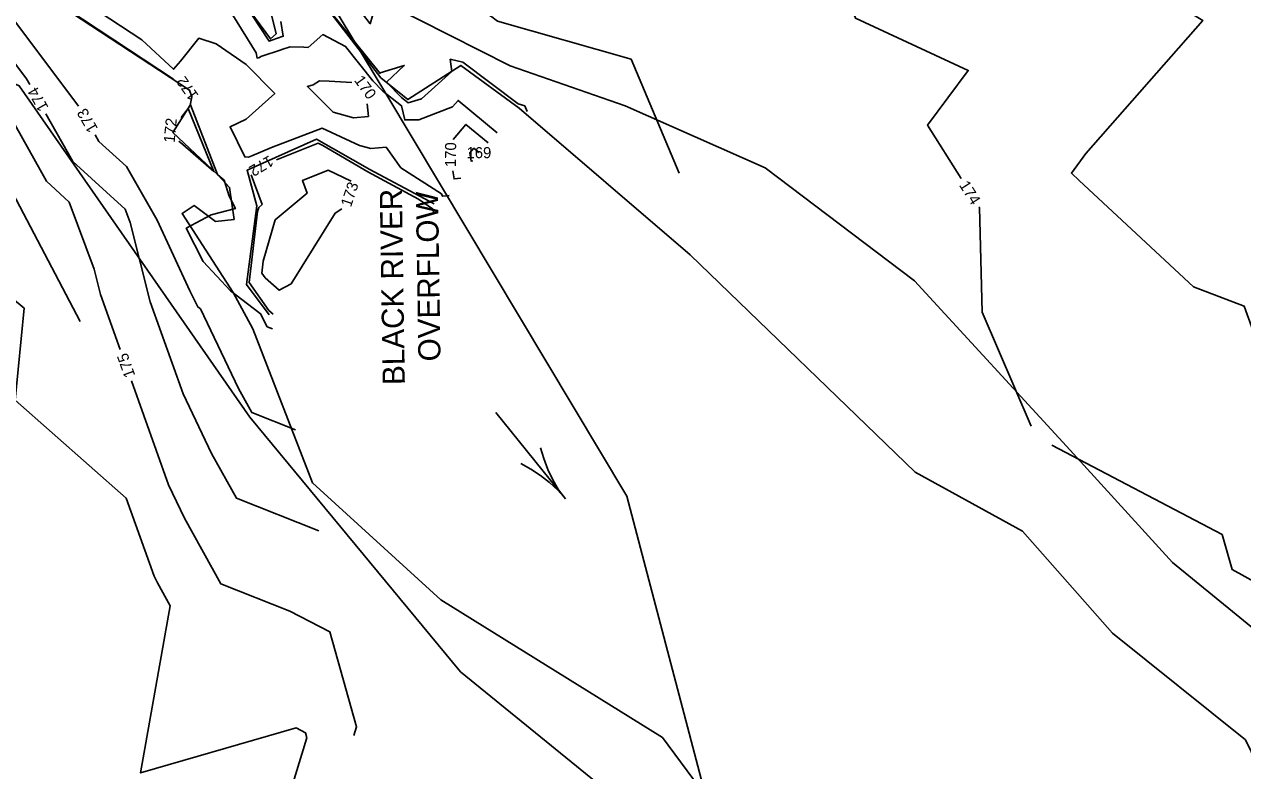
# Model space of a CAD drawing. Extents: x 2086416 to 2115205, y 575507 to 632762.
# Drawn here: x 2111556.7 to 2111776.5, y 581467.3 to 581601.8 of the extents above; entities that cross this region are included whole.
import ezdxf

# ---------------------------------------------------------------- set-up
doc = ezdxf.new("R2010")
doc.units = 0
for name, color, linetype in [('DTM Contours Major', 7, 'Continuous'), ('DTM Contours Major Text', 7, 'Continuous'), ('DTM Contours Minor', 7, 'Continuous'), ('DTM Contours Minor Text', 7, 'Continuous'), ('Exist Hydro River Flow Arrow CELL', 7, 'Continuous'), ('Exist Hydro Stream or Body of Water', 7, 'Continuous'), ('Exist Hydro Stream or Body of Water Text', 7, 'Continuous'), ('Exist Hydrographic Stream Bed', 7, 'Continuous'), ('Exist Vegetation Woods Line', 7, 'Continuous')]:
    doc.layers.add(name, color=color, linetype=linetype)

msp = doc.modelspace()

# ---------------------------------------------------------------- linework, layer by layer
at = {"layer": 'DTM Contours Major'}
for points in [[(2111534.94, 581633.7), (2111534.95, 581633.69), (2111540.69, 581621.59), (2111540.75, 581620.7), (2111543.07, 581605.02), (2111543.15, 581604.73), (2111546.21, 581598.92), (2111547.25, 581597.53), (2111560.71, 581573.54), (2111564.82, 581569.8), (2111569.33, 581557.68), (2111570.48, 581553.11), (2111574.03, 581543.19)], [(2111780.53, 581536.2), (2111779.91, 581542.21), (2111776.72, 581551.05), (2111767.61, 581554.53), (2111746.99, 581573.66), (2111745.59, 581575.02), (2111748.2, 581578.53), (2111769.31, 581602.49), (2111766.72, 581604.09), (2111762.55, 581607.47)], [(2111612.41, 581585.98), (2111607.79, 581590.61), (2111608.83, 581590.91), (2111609.95, 581591.62), (2111611.71, 581591.58), (2111615.79, 581591.34)], [(2111618.56, 581587.48), (2111618.79, 581585.22), (2111616.06, 581585), (2111612.41, 581585.98)], [(2111640.37, 581580.48), (2111636.37, 581583.8), (2111634.08, 581581.09)], [(2111634.02, 581575.42), (2111634.23, 581573.95), (2111635.48, 581574.08)], [(2111576.05, 581537.54), (2111582.75, 581518.81), (2111585.61, 581512.82), (2111592.18, 581500.96), (2111604.59, 581496.05), (2111611.81, 581492.33), (2111616.64, 581475.22), (2111616.16, 581473.64)]]:
    msp.add_lwpolyline(points, dxfattribs=at)
at = {"layer": 'DTM Contours Minor'}
for points in [[(2111577.85, 581632.76), (2111579.38, 581631.77), (2111585.59, 581622.88), (2111586.9, 581621.52), (2111588.77, 581619.19), (2111592.83, 581615.07), (2111599.25, 581613.25), (2111610.21, 581607.89), (2111612.26, 581606.57), (2111617.7, 581603.71), (2111619.12, 581601.94), (2111619.52, 581603.35), (2111619.22, 581603.58), (2111621.46, 581611.66), (2111622.11, 581614.01), (2111639.99, 581603.54), (2111640.81, 581603.36), (2111642.08, 581602.39), (2111666.16, 581595.53), (2111674.85, 581575.03)], [(2111589.24, 581620.71), (2111589.88, 581619.92), (2111590.86, 581618.93), (2111592.4, 581618.49), (2111599.33, 581615.1), (2111605.37, 581623.89), (2111605.71, 581625.53), (2111604.66, 581629.9), (2111612.58, 581630.28), (2111613.26, 581630.39), (2111619.38, 581630.75), (2111621.02, 581630.79), (2111642.89, 581633.66), (2111647.2, 581633.15), (2111648.46, 581631.54), (2111653.2, 581633.04), (2111670.86, 581631.97), (2111682.2, 581631.35), (2111685.06, 581615.46), (2111702.13, 581615.46), (2111706.66, 581602.93), (2111726.97, 581593.52), (2111719.65, 581583.63), (2111725.71, 581574.01)], [(2111549.08, 581629.05), (2111561.22, 581607.23), (2111561.71, 581606.42), (2111583.6, 581591.95)], [(2111554.71, 581624.02), (2111564.46, 581607.91), (2111577.89, 581599.03), (2111583.64, 581593.74), (2111584.9, 581595.2), (2111588.2, 581599.36), (2111591.32, 581598.31), (2111596.72, 581594.56), (2111601.88, 581589.39), (2111596.72, 581584.75), (2111593.84, 581583.38), (2111596.47, 581577.94), (2111597.16, 581577.87), (2111597.78, 581578.11), (2111601.3, 581579.62), (2111610.43, 581583.11), (2111617.16, 581580.01), (2111619.2, 581579.46), (2111621.97, 581579.69), (2111624.61, 581575.97), (2111631.97, 581571.27), (2111632.13, 581570.83), (2111633.37, 581570.96)], [(2111642, 581582.26), (2111634.94, 581588.12), (2111633.95, 581586.96), (2111627.89, 581584.61), (2111625.34, 581584.6), (2111624.75, 581587.14), (2111621.39, 581589.78), (2111619.57, 581591.62), (2111614.67, 581597.85), (2111610.55, 581599.98), (2111607.93, 581597.67), (2111607.12, 581597.71), (2111604.69, 581597.77), (2111603.18, 581597.28), (2111603.05, 581597.24), (2111599.38, 581596.01), (2111599.14, 581595.86), (2111598.69, 581595.73), (2111598.53, 581596.66), (2111585.91, 581617.09)], [(2111596.14, 581605.98), (2111600.86, 581598.82), (2111601.33, 581598.98), (2111602.4, 581599.34), (2111603.42, 581599.67), (2111602.97, 581602.32)], [(2111553.76, 581604.05), (2111566.51, 581587.07)], [(2111611.76, 581604.31), (2111620.89, 581592.97), (2111620.93, 581593.1), (2111625.25, 581594.41), (2111622.03, 581591.39), (2111624.75, 581588.65), (2111625.98, 581587.68), (2111628.35, 581588.4), (2111633.8, 581593.35), (2111633.55, 581595.53), (2111635.83, 581595.02), (2111645.81, 581587.47), (2111646.98, 581587.13), (2111647.4, 581586.14)], [(2111549.98, 581601.49), (2111557.09, 581592.02), (2111557.69, 581590.96)], [(2111590.91, 581575.33), (2111586.27, 581586.68), (2111584.99, 581585.04)], [(2111586.68, 581587.63), (2111586.69, 581587.52), (2111586.67, 581587.29), (2111591.57, 581574.78), (2111591.61, 581574.7), (2111591.64, 581574.7), (2111592.77, 581573.73), (2111593.64, 581570.85), (2111594.79, 581568.61), (2111590.43, 581567.52), (2111585.93, 581565.06), (2111588.98, 581559.07), (2111593.91, 581553.81), (2111599, 581549.88), (2111599.4, 581549.59), (2111600.23, 581547.84), (2111600.52, 581547.32), (2111601.48, 581546.94)], [(2111560.62, 581585.72), (2111565.44, 581577.12), (2111574.93, 581568.49), (2111575.82, 581566.12), (2111579.43, 581551.8), (2111585.36, 581535.23), (2111590.48, 581524.5), (2111594.96, 581516.42), (2111609.82, 581510.54)], [(2111569.52, 581581.89), (2111570.18, 581580.71), (2111575.13, 581576.21), (2111580.7, 581566.52), (2111586.55, 581553.77), (2111588.02, 581550.88), (2111588.51, 581550.52), (2111595.36, 581536.17), (2111597.74, 581531.87), (2111605.65, 581528.74)], [(2111584.58, 581580.78), (2111585.3, 581580.18), (2111590.91, 581575.33)], [(2111631.25, 581567.84), (2111630.64, 581567.77), (2111630.35, 581568.58), (2111627.82, 581570.29), (2111618.68, 581575.23), (2111610.55, 581580), (2111609.72, 581580.4), (2111602.22, 581577.39)], [(2111638.74, 581578.7), (2111637.8, 581579.48), (2111637.09, 581578.64), (2111637.3, 581577.17), (2111637.6, 581577.2)], [(2111599.54, 581557), (2111599.79, 581559.16), (2111601.98, 581566.57), (2111607.71, 581571.38), (2111606.88, 581573.67), (2111611.5, 581575.52), (2111615.66, 581573.56)], [(2111597.64, 581574.71), (2111599.59, 581569.33), (2111599.01, 581568.84), (2111598.78, 581568.09), (2111597.29, 581555.28), (2111600.81, 581550.27), (2111601.6, 581549.57)], [(2111614, 581568.6), (2111612.79, 581567.81), (2111604.84, 581555.04), (2111602.67, 581553.89), (2111600.13, 581556.16), (2111599.54, 581557)], [(2111728.9, 581568.93), (2111728.98, 581568.81), (2111729.5, 581549.93), (2111738.35, 581529.42)], [(2111549.42, 581565.48), (2111549.3, 581556.75), (2111556.68, 581550.67), (2111555.04, 581534.11), (2111575.11, 581516.45), (2111580.14, 581502.39), (2111580.74, 581501.15), (2111583.03, 581497), (2111577.68, 581466.9), (2111605.74, 581475), (2111607.43, 581474.14), (2111607.69, 581473.21), (2111591.9, 581421.84), (2111590.92, 581419.37), (2111591.04, 581419.17), (2111590.97, 581419.11)], [(2111795.57, 581491.95), (2111774.6, 581503.54), (2111772.79, 581509.85), (2111742.06, 581525.95)]]:
    msp.add_lwpolyline(points, dxfattribs=at)
at = {"layer": 'Exist Hydro River Flow Arrow CELL'}
for p, q in [((2111654.32, 581516.29), (2111641.77, 581531.86)), ((2111649.82, 581525.51), (2111650.4, 581523.55)), ((2111646.26, 581522.64), (2111648.06, 581521.67)), ((2111648.04, 581524.08), (2111648.04, 581524.08)), ((2111650.4, 581523.55), (2111651.14, 581521.61)), ((2111648.06, 581521.67), (2111649.8, 581520.53)), ((2111649.8, 581520.53), (2111651.44, 581519.24)), ((2111651.14, 581521.61), (2111652.05, 581519.73)), ((2111651.44, 581519.24), (2111652.97, 581517.84)), ((2111652.05, 581519.73), (2111653.09, 581517.93)), ((2111653.09, 581517.93), (2111654.32, 581516.29)), ((2111652.97, 581517.84), (2111654.32, 581516.29))]:
    msp.add_line(p, q, dxfattribs=at)
at = {"layer": 'Exist Hydro Stream or Body of Water'}
msp.add_line((2111630.63, 581569.49), (2111619.04, 581575.64), dxfattribs=at)
for points in [[(2111591.59, 581574.69), (2111583.51, 581582.32), (2111586.65, 581587.28), (2111586.9, 581588.76), (2111586.51, 581589.98), (2111561.57, 581606.34), (2111549, 581629.07), (2111542.47, 581641.26), (2111541.35, 581641.18), (2111528.82, 581652.89), (2111524.36, 581663.91), (2111523.31, 581667.75), (2111502.68, 581682.78), (2111481.94, 581698.46), (2111468.58, 581724.28), (2111463, 581737.48)], [(2111621.04, 581592.2), (2111611.64, 581604.33), (2111605.91, 581608.14), (2111600.48, 581607.01), (2111602.12, 581600.1), (2111601.11, 581599.2), (2111587.78, 581617.38), (2111576.69, 581633.34), (2111571.48, 581641.08), (2111570.64, 581641.03), (2111569.87, 581645.92), (2111561.21, 581659.64), (2111560.4, 581669.08), (2111561.77, 581674.66), (2111567.14, 581693.15), (2111571.77, 581696.53), (2111557.1, 581714.2), (2111551.35, 581722.03)], [(2111621.04, 581592.2), (2111625.87, 581588.27), (2111635.48, 581594.43), (2111646, 581586.7)], [(2111785.01, 581456.38), (2111776.98, 581472.85), (2111753.02, 581492.1), (2111736.76, 581510.47), (2111717.38, 581521.12), (2111676.84, 581560.27), (2111646, 581586.7)], [(2111600.9, 581549.46), (2111596.8, 581554.91), (2111598.67, 581569.1), (2111596.9, 581575.53), (2111609.44, 581581.15), (2111619.04, 581575.64)], [(2111597.94, 581546.96), (2111594.36, 581553.52), (2111585.17, 581567.74), (2111587.38, 581569.17), (2111591.18, 581566.27), (2111594.55, 581566.67), (2111593.73, 581572.44), (2111591.59, 581574.69)], [(2111597.94, 581546.96), (2111608.71, 581519.2), (2111631.83, 581498.07), (2111671.82, 581473.29), (2111688.43, 581450.85), (2111710.78, 581426.78), (2111742.36, 581409.74), (2111754.48, 581398.89), (2111760.49, 581379.8)]]:
    msp.add_lwpolyline(points, dxfattribs=at)
at = {"layer": 'Exist Hydrographic Stream Bed'}
msp.add_lwpolyline([(2112129.65, 582477.71), (2111835.9, 582368.96), (2111727.15, 582231.15), (2111672.65, 582129.59), (2111610.9, 582009.96), (2111585.65, 581897.53), (2111574.65, 581806.9), (2111574.65, 581727.08), (2111582.9, 581679.52), (2111589.15, 581643.7), (2111621.9, 581589.33), (2111665.4, 581516.77), (2111701.65, 581379.01), (2111737.9, 581248.45), (2111785.15, 581103.39)], dxfattribs=at)
at = {"layer": 'Exist Vegetation Woods Line'}
for points in [[(2111779.57, 581491.97), (2111763.79, 581504.85), (2111745.34, 581525.06), (2111717.3, 581555.59), (2111690.35, 581575.95), (2111665.09, 581587.14), (2111644.35, 581594.34), (2111622.46, 581605.4), (2111614.18, 581617.92), (2111615.41, 581630.25), (2111644.69, 581636.02), (2111711.67, 581643.9), (2111763.23, 581655.57), (2111785.51, 581656)], [(2111257.87, 581581.4), (2111333.1, 581590.97), (2111406.18, 581600.07), (2111473.94, 581614.42), (2111501.63, 581613.42), (2111525.04, 581604.65), (2111555.79, 581590.73), (2111597.41, 581531.02), (2111635.4, 581485.12), (2111692.38, 581438.81), (2111736.92, 581397.7), (2111757.96, 581379.06)], [(2111566.76, 581548.29), (2111551.99, 581576.31), (2111385.4, 581583.05), (2111297.09, 581569.27), (2111253.55, 581562.72), (2111242.01, 581577.17), (2111257.87, 581581.4)]]:
    msp.add_lwpolyline(points, dxfattribs=at)

# ---------------------------------------------------------------- texts
at = {"layer": 'DTM Contours Major Text'}
for s, rotation, p in [('170', 305.7255, (2111616.12, 581591.73)), ('170', 89.445, (2111634.57, 581576.1)), ('175', 109.6834, (2111576.75, 581538.56))]:
    msp.add_text(s, height=2, rotation=rotation, dxfattribs=at).set_placement(p)
at = {"layer": 'DTM Contours Minor Text'}
for s, rotation, p in [('174', 119.2876, (2111561.14, 581586.84)), ('172', 125.4721, (2111588.24, 581589.02)), ('173', 120.1544, (2111570.06, 581583.04)), ('172', 84.6087, (2111583.82, 581580.4)), ('172', 210.2842, (2111600.9, 581578.28)), ('173', 71.5054, (2111615.62, 581568.76)), ('174', 302.1749, (2111725.25, 581572.86))]:
    msp.add_text(s, height=2, rotation=rotation, dxfattribs=at).set_placement(p)
msp.add_text('169', height=2, dxfattribs=at).set_placement((2111636.48, 581577.7))
at = {"layer": 'Exist Hydro Stream or Body of Water Text'}
for s, p in [('BLACK RIVER', (2111625.36, 581536.84)), ('OVERFLOW', (2111631.8, 581541.11))]:
    msp.add_text(s, height=4, rotation=90.8753, dxfattribs=at).set_placement(p)

doc.saveas('drawing.dxf')
